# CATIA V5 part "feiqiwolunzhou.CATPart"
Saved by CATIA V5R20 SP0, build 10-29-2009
Part number: feiqiwolunzhou
Material "无"
Bounding box of the stored display mesh (mm): x -5 to 5, y -5 to 5, z -97 to 60
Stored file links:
  C:\Users\Administrator\Desktop\feiqiwolunzhou.CATPart
  C:\Users\Administrator\Desktop\ZENGYAQI.CATProduct
  C:\Users\Administrator\Desktop\paiqiwolunke.CATPart
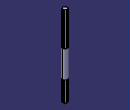
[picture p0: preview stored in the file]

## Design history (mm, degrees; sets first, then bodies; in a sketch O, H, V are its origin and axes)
Body1 (main body), material "无"
  DatumCurve1 to DatumCurve24
  Sketch1 on xy-plane, origin (0, 0, 0), H (1, 0, 0), V (0, 1, 0)
    projected arc E1 centre (0, 0) radius 3.5 from (-0.6, 3.4482) to (-2.6862, 2.2437) ccw from edge of DatumCurve1
    projected line E2 (-3.7254, 2.8437) -> (-2.6862, 2.2437) from edge of DatumCurve2
    projected line E3 (-4.3254, 1.8045) -> (-3.7254, 2.8437) from edge of DatumCurve3
    projected line E4 (-3.2862, 1.2045) -> (-4.3254, 1.8045) from edge of DatumCurve4
    projected arc E5 centre (0, 0) radius 3.5 from (-3.2862, 1.2045) to (-3.2862, -1.2045) ccw from edge of DatumCurve5
    projected line E6 (-4.3254, -1.8045) -> (-3.2862, -1.2045) from edge of DatumCurve6
    projected line E7 (-3.7254, -2.8437) -> (-4.3254, -1.8045) from edge of DatumCurve7
    projected line E8 (-2.6862, -2.2437) -> (-3.7254, -2.8437) from edge of DatumCurve8
    projected arc E9 centre (0, 0) radius 3.5 from (-2.6862, -2.2437) to (-0.6, -3.4482) ccw from edge of DatumCurve9
    projected line E10 (-0.6, -4.6482) -> (-0.6, -3.4482) from edge of DatumCurve10
    projected line E11 (0.6, -4.6482) -> (-0.6, -4.6482) from edge of DatumCurve11
    projected line E12 (0.6, -3.4482) -> (0.6, -4.6482) from edge of DatumCurve12
    projected arc E13 centre (0, 0) radius 3.5 from (0.6, -3.4482) to (2.6862, -2.2437) ccw from edge of DatumCurve13
    projected line E14 (3.7254, -2.8437) -> (2.6862, -2.2437) from edge of DatumCurve14
    projected line E15 (4.3254, -1.8045) -> (3.7254, -2.8437) from edge of DatumCurve15
    projected line E16 (3.2862, -1.2045) -> (4.3254, -1.8045) from edge of DatumCurve16
    projected arc E17 centre (0, 0) radius 3.5 from (3.2862, -1.2045) to (3.2862, 1.2045) ccw from edge of DatumCurve17
    projected line E18 (4.3254, 1.8045) -> (3.2862, 1.2045) from edge of DatumCurve18
    projected line E19 (3.7254, 2.8437) -> (4.3254, 1.8045) from edge of DatumCurve19
    projected line E20 (2.6862, 2.2437) -> (3.7254, 2.8437) from edge of DatumCurve20
    projected arc E21 centre (0, 0) radius 3.5 from (2.6862, 2.2437) to (0.6, 3.4482) ccw from edge of DatumCurve21
    projected line E22 (0.6, 4.6482) -> (0.6, 3.4482) from edge of DatumCurve22
    projected line E23 (-0.6, 4.6482) -> (0.6, 4.6482) from edge of DatumCurve23
    projected line E24 (-0.6, 3.4482) -> (-0.6, 4.6482) from edge of DatumCurve24
  Pad1: profile Sketch1, direction (0, 0, 1), length 60, opposite side length 5
  Sketch2 on start face of Pad1, origin (0, 0, -5), H (1, 0, 0), V (0, 1, 0)
    circle A1 centre (0, 0) radius 5
    point P1 (0, 5)
    radius A1 = 5
    coincidence: A1 P1, P1 V
  Pad2: profile Sketch2, direction (0, 0, -1), length 52
  Sketch3 on end face of Pad2, origin (0, 0, -57), H (1, 0, 0), V (0, 1, 0)
    projected line E1 (0.6, -4.6482) -> (-0.6, -4.6482) from edge of DatumCurve11
    projected line E2 (0.6, -3.4482) -> (0.6, -4.6482) from edge of DatumCurve12
    projected arc E3 centre (0, 0) radius 3.5 from (0.6, -3.4482) to (2.6862, -2.2437) ccw from edge of DatumCurve13
    projected line E4 (3.7254, -2.8437) -> (2.6862, -2.2437) from edge of DatumCurve14
    projected line E5 (4.3254, -1.8045) -> (3.7254, -2.8437) from edge of DatumCurve15
    projected arc E6 centre (0, 0) radius 3.5 from (3.2862, -1.2045) to (3.2862, 1.2045) ccw from edge of DatumCurve17
    projected line E7 (3.2862, -1.2045) -> (4.3254, -1.8045) from edge of DatumCurve16
    projected line E8 (4.3254, 1.8045) -> (3.2862, 1.2045) from edge of DatumCurve18
    projected line E9 (3.7254, 2.8437) -> (4.3254, 1.8045) from edge of DatumCurve19
    projected line E10 (2.6862, 2.2437) -> (3.7254, 2.8437) from edge of DatumCurve20
    projected arc E11 centre (0, 0) radius 3.5 from (2.6862, 2.2437) to (0.6, 3.4482) ccw from edge of DatumCurve21
    projected line E12 (0.6, 4.6482) -> (0.6, 3.4482) from edge of DatumCurve22
    projected line E13 (-0.6, 4.6482) -> (0.6, 4.6482) from edge of DatumCurve23
    projected line E14 (-0.6, 3.4482) -> (-0.6, 4.6482) from edge of DatumCurve24
    projected arc E15 centre (0, 0) radius 3.5 from (-0.6, 3.4482) to (-2.6862, 2.2437) ccw from edge of DatumCurve1
    projected line E16 (-3.7254, 2.8437) -> (-2.6862, 2.2437) from edge of DatumCurve2
    projected line E17 (-4.3254, 1.8045) -> (-3.7254, 2.8437) from edge of DatumCurve3
    projected line E18 (-3.2862, 1.2045) -> (-4.3254, 1.8045) from edge of DatumCurve4
    projected arc E19 centre (0, 0) radius 3.5 from (-3.2862, 1.2045) to (-3.2862, -1.2045) ccw from edge of DatumCurve5
    projected line E20 (-4.3254, -1.8045) -> (-3.2862, -1.2045) from edge of DatumCurve6
    projected line E21 (-3.7254, -2.8437) -> (-4.3254, -1.8045) from edge of DatumCurve7
    projected line E22 (-2.6862, -2.2437) -> (-3.7254, -2.8437) from edge of DatumCurve8
    projected arc E23 centre (0, 0) radius 3.5 from (-2.6862, -2.2437) to (-0.6, -3.4482) ccw from edge of DatumCurve9
    projected line E24 (-0.6, -4.6482) -> (-0.6, -3.4482) from edge of DatumCurve10
  Pad3: profile Sketch3, direction (0, 0, -1), length 40
  Plane1: linked copy from another document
